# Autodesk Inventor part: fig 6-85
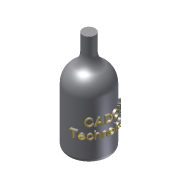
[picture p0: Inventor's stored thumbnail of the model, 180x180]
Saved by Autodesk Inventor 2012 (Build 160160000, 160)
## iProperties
Shininess: 64.0
Length Units: 11269
Angle Units: 11279
Time Units: 11290
Mass Units: 11283
Length Display Precision: 3
Angle Display Precision: 2
Compacted: True
Part Number: fig 6-85
Document SubType Name: Modeling
Created: 2002-12
Designer: deepak
Density: 1 g/cm^3
Material: Default
Density: 0.0
Volumn: 0.0
Area: 0.0
PropertySet Name: Model Information
Control State: 0
Master: False
Checked Out: False
Author: deepak
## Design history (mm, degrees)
node "Sketch1"
sketch "Sketch2"
  geometry: L1 (-7.653, 24.992)-(-7.653, 16.776); L2 (-14.653, 3.659)-(-14.653, -3.57); L3 (-14.653, -3.57)-(-14.653, -23.329); L4 (-14.653, -23.329)-(-4.653, -23.329); L5 (-4.653, -23.329)-(-4.653, 24.992); L6 (-4.653, 24.992)-(-7.653, 24.992); A1 r 6.757 centre (-14.41, 16.776) between (-10.649, 11.163) and (-7.653, 16.776); A2 r 9.033 centre (-5.62, 3.659) between (-10.649, 11.163) and (-14.653, 3.659)
  constraints: 12 end point, 4 point on circle, 3 tangent, 2 centre point, 2 parallel, 2 perpendicular, 1 collinear, 1 vertical
  dimensions: "d0" = 3 distance of L5.end L1.start; "d1" = 10 distance of L3.end L4.end
revolve "Revolution1" sketch "Sketch2" stored, may be unused: angle "d2" = 90 deg
fillet "Fillet1" dims "d3" = 2
workplane "Work Plane1"
workplane "Work Plane2"
sketch "Sketch3"
  geometry: L1 (-24.815, -3.793)-(24.913, -3.793); L2 (24.913, -3.793)-(24.913, -8.382); L3 (24.913, -8.382)-(-24.815, -8.382); L4 (-24.815, -8.382)-(-24.815, -3.793)
  constraints: 2 other
emboss "Emboss1" sketch "Sketch3" dims "d5" = 1, "d6" = 0
body "Solid1"
other parameters: "d4" = 3.5
